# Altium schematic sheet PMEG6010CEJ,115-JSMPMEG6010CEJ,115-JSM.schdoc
size 127 x 101 mm
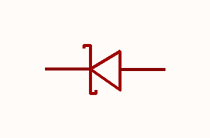
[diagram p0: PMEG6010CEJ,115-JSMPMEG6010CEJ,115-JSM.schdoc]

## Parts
D?  pmeg6010cej,115-jsm  [SOD-323_L1.7-W1.3-LS2.5-RD]  (value not drawn)

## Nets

Not connected (* = marked no-connect by the designer): D? 1(C) 2(A)

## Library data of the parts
D? = pmeg6010cej,115-jsm: 二极管配置:1个独立式;正向压降(Vf):700mV@1A;直流反向耐压(Vr):60V;整流电流:1A;; Manufacturer: JSMSEMI(杰盛微); AddInBom: yes; ModelId: 0f2f330c645944df9245ac3c3fec3456; ModelName: SOD-323_L1.7-W1.3-LS2.5-FD; ModelTransform: 98.425,49.2125,0,0,0,0,0,0,0; Diode Configuration: 1个独立式; Voltage - DC Reverse(Vr): 60V; Current - Rectified: 1A; Reverse Leakage Current (Ir): 100uA@60V; Non-Repetitive Peak Forward Surge Current: 25A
